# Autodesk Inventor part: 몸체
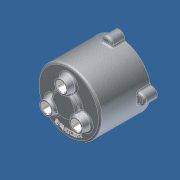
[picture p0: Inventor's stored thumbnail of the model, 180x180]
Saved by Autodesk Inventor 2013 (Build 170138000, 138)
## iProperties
Company: 한국ATC센터
Created: 2014-07
Part Number: 몸체
Document SubType Name: 모델링
Designer: KYOUNG IL JANG
Material: Generic
변환 표준: STEP AP214IS
파일 이름: C:\Users\SeoGD\Desktop\?쒗뿕\紐몄껜.stp
전처리기: Build: 253, Release: 2010 SP1 - Date: Wed 07/29/2009
전송 단위: 밀리미터
불확실성: 0.01
Author: KYOUNG IL JANG
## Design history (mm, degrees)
sketch "스케치2"
  geometry: C1 r 50 at (0, 0); 1 further point
  constraints: 1 centre point, 1 coincident
  dimensions: "d9" = 100 diameter of C1
extrude "돌출2" new body sketch "스케치2" distance "d10" = 80; taper "d11" = 0 deg
feature "쉘1" dims "d12" = 5
sketch "스케치3" dims "d13" = 55
  geometry: C1 r 7.5 at (0, 27.5); C2 r 12.5 at (0, 27.5); 2 further points
  constraints: 2 centre point, 2 coincident, 2 vertical alignment, 2 other
  dimensions: "d14" = 15 diameter of C1; "d15" = 25 diameter of C2
extrude "돌출3" join sketch "스케치3" distance "d16" = 12; taper "d17" = -10 deg
hole "구멍2" diameter "d20" = 15; stored, may be unused: countersink angle "d24" = 90 deg, drill point angle "d26" = 118 deg; dims "d18" = 10, "d19" = 10, "d21" = 6, "d22" = 4, "d23" = 2, "d25" = 15
chamfer "모따기1" distance "d27" = 1; stored, may be unused: second distance "d28" = 2, angle "d29" = 45 deg
revolve "회전1" stored, may be unused: angle "d38" = 90 deg
hole "구멍3" diameter "d41" = 15; stored, may be unused: countersink angle "d45" = 90 deg, drill point angle "d47" = 0 deg; dims "d39" = 10, "d40" = 10, "d42" = 6, "d43" = 22, "d44" = 13, "d46" = 15
chamfer "모따기2" distance "d48" = 1; stored, may be unused: second distance "d49" = 2, angle "d50" = 45 deg
fillet "모깎기1" dims "d52" = 3
fillet "모깎기2" dims "d53" = 3, "d72" = 0.2
sketch "스케치5"
  geometry: A1 r 50 centre (0, 0) between (50, 0) and (-8.074, 49.344) reference; A2 r 8.5 centre (0, 52) between (8.074, 49.344) and (-8.074, 49.344); 1 further point
  constraints: 5 point on circle, 1 centre point, 1 horizontal alignment
  dimensions: "d54" = 90 deg dimension on point (0, 0) A2.centre A1.start; "d55" = 52 distance of A2.centre point (0, 0); "d56" = 17 diameter of A2
extrude "돌출4" join sketch "스케치5" distance "d57" = 20; taper "d58" = 0 deg
fillet "모깎기3" dims "d59" = 3
hole "구멍4" diameter "d62" = 4.134; stored, may be unused: countersink angle "d66" = 90 deg, drill point angle "d68" = 118 deg; dims "d60" = 10, "d61" = 10, "d63" = 12, "d64" = 22, "d65" = 13, "d67" = 15
feature "엠보싱1" dims "d74" = 1, "d75" = 0
node "솔리드1"
node "솔리드 본체"
node "곡면 본체"
pattern_circular "원형 패턴1" dims "d31" = 360 deg
pattern_circular "원형 패턴2" dims "d70" = 360 deg
node "솔리드2"
sketch "스케치4"
  geometry: L1 (0, 0)-(0, 88); L2 (0, 70)-(13.16, 70); L3 (-45, 75)-(45, 75) reference; L4 (-50, 80)-(50, 80) reference; L5 (13.16, 70)-(14.5, 75); L6 (20, 80)-(20, 88); L7 (20, 88)-(0, 88); L8 (20, 80)-(14.5, 75)
  constraints: 12 end point, 3 point on line, 2 perpendicular, 1 vertical
  dimensions: "d34" = 40 diameter of L6 L1; "d35" = 105 deg angle of L5 L3; "d36" = 5 distance between parallel lines of L2 L3; "d37" = 8 distance between parallel lines of L7 L4; "d51" = 29 diameter of L5.end L1
sketch "스케치6"
  geometry: C1 r 47 at (0, 0) reference; C2 r 42.5 at (0, 0); 1 further point
  constraints: 1 centre point, 1 coincident, 1 other
  dimensions: "d73" = 85 diameter of C2
